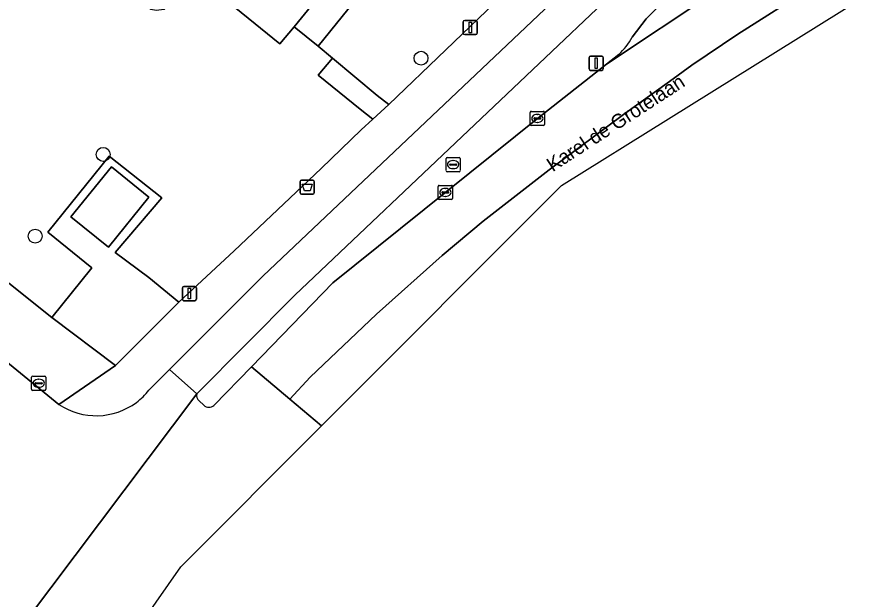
# Model space of a CAD drawing. Extents: x 159674 to 160531, y 382172 to 382904.
# Drawn here: x 160403.6 to 160463.2, y 382615.6 to 382656.6 of the extents above; entities that cross this region are included whole.
import ezdxf

# ---------------------------------------------------------------- set-up
doc = ezdxf.new("R2010")
doc.units = 0
for name, color, linetype in [('IMGEO_Afvalbak', 7, 'Continuous'), ('IMGEO_Boom', 7, 'Continuous'), ('IMGEO_Fietspad_gesloten', 7, 'Continuous'), ('IMGEO_Groenvoorziening', 7, 'Continuous'), ('IMGEO_Kolk', 7, 'Continuous'), ('IMGEO_Lichtmast', 7, 'Continuous'), ('IMGEO_Openbare_ruimte_label', 7, 'Continuous'), ('IMGEO_Pand', 7, 'Continuous'), ('IMGEO_Rijbaan_lokaal_gesloten', 7, 'Continuous'), ('IMGEO_Rijbaan_lokaal_open', 7, 'Continuous'), ('IMGEO_Rioolput', 7, 'Continuous'), ('IMGEO_Voetpad_open', 7, 'Continuous')]:
    doc.layers.add(name, color=color, linetype=linetype)

msp = doc.modelspace()

# ---------------------------------------------------------------- linework, layer by layer
at = {"layer": 'IMGEO_Afvalbak'}
for p, q in [((160423.555, 382644.212), (160423.555, 382645.012)), ((160423.555, 382645.012), (160423.555, 382644.212)), ((160423.655, 382645.112), (160424.445, 382645.112)), ((160424.445, 382645.112), (160423.655, 382645.112)), ((160424.545, 382645.012), (160424.545, 382644.212)), ((160424.545, 382644.212), (160424.545, 382645.012)), ((160424.445, 382644.112), (160423.655, 382644.112)), ((160423.655, 382644.112), (160424.445, 382644.112))]:
    msp.add_line(p, q, dxfattribs=at)
msp.add_lwpolyline([(160423.698, 382644.826), (160424.402, 382644.826), (160424.253, 382644.356), (160423.847, 382644.356), (160423.698, 382644.826)], dxfattribs=at)
for centre, start, end in [((160423.655, 382645.012), 90, 180), ((160423.655, 382645.012), 90, 180), ((160424.445, 382645.012), 0, 90), ((160424.445, 382645.012), 360, 90), ((160423.655, 382644.212), 180, 270), ((160423.655, 382644.212), 180, 270), ((160424.445, 382644.212), 270, 0), ((160424.445, 382644.212), 270, 0)]:
    msp.add_arc(centre, 0.1, start, end, dxfattribs=at)
at = {"layer": 'IMGEO_Boom'}
for centre in [(160432.057, 382653.687), (160409.684, 382646.916), (160404.9, 382641.156)]:
    msp.add_circle(centre, 0.489, dxfattribs=at)
at = {"layer": 'IMGEO_Fietspad_gesloten'}
msp.add_lwpolyline([(160481.633, 382696.489), (160468.127, 382683.364), (160447.776, 382663.816), (160420.944, 382638.37), (160414.361, 382631.767), (160416.285, 382630.052), (160423.176, 382637.014), (160449.405, 382661.919)], dxfattribs=at)
at = {"layer": 'IMGEO_Groenvoorziening'}
for points in [[(160458.672, 382690.773), (160458.911, 382690.581), (160460.799, 382692.927), (160459.501, 382693.982), (160460.055, 382694.663), (160458.322, 382696.07), (160458.645, 382696.467), (160455.839, 382698.746), (160454.066, 382700.186), (160451.285, 382696.761), (160455.9, 382693.013), (160456.251, 382693.445), (160457.39, 382692.52), (160454.167, 382688.552), (160441.841, 382673.375), (160439.126, 382675.58), (160433.895, 382669.14), (160423.117, 382655.907), (160424.815, 382654.532), (160438.917, 382671.995), (160441.694, 382669.745)], [(160465.663, 382685.146), (160458.911, 382690.581), (160458.672, 382690.773), (160441.694, 382669.745), (160438.917, 382671.995), (160424.815, 382654.532), (160425.817, 382653.69), (160428.959, 382651.052), (160429.794, 382650.429), (160445.842, 382665.847)]]:
    msp.add_lwpolyline(points, close=True, dxfattribs=at)
msp.add_lwpolyline([(160378.286, 382657.664), (160406.072, 382635.422), (160408.896, 382638.927), (160405.782, 382641.438), (160410.1, 382646.796), (160413.826, 382643.859), (160410.536, 382640.006), (160412.902, 382638.241), (160415.013, 382636.511), (160418.91, 382640.121), (160425.018, 382645.922), (160427.834, 382648.645), (160428.66, 382649.405), (160427.78, 382650.092), (160424.82, 382652.503), (160425.817, 382653.69), (160424.815, 382654.532), (160423.117, 382655.907), (160422.13, 382654.694), (160416.298, 382659.444)], dxfattribs=at)
at = {"layer": 'IMGEO_Kolk'}
for p, q in [((160439.742, 382649.022), (160439.742, 382649.874)), ((160439.817, 382649.948), (160440.669, 382649.948)), ((160440.23, 382649.728), (160440.255, 382649.728)), ((160440.743, 382649.874), (160440.743, 382649.022)), ((160440.001, 382649.442), (160440.001, 382649.454)), ((160440.439, 382649.405), (160440.041, 382649.405)), ((160440.044, 382649.491), (160440.442, 382649.491)), ((160440.253, 382649.168), (160440.228, 382649.168)), ((160440.485, 382649.454), (160440.485, 382649.442)), ((160440.669, 382648.948), (160439.817, 382648.948)), ((160433.269, 382643.81), (160433.269, 382644.662)), ((160433.344, 382644.736), (160434.196, 382644.736)), ((160433.528, 382644.23), (160433.528, 382644.242)), ((160433.966, 382644.193), (160433.568, 382644.193)), ((160433.571, 382644.279), (160433.969, 382644.279)), ((160433.757, 382644.516), (160433.782, 382644.516)), ((160434.012, 382644.242), (160434.012, 382644.23)), ((160434.27, 382644.662), (160434.27, 382643.81)), ((160434.196, 382643.736), (160433.344, 382643.736)), ((160433.78, 382643.956), (160433.755, 382643.956)), ((160404.652, 382630.371), (160404.652, 382631.223)), ((160404.727, 382631.297), (160405.579, 382631.297)), ((160405.653, 382631.223), (160405.653, 382630.371)), ((160404.911, 382630.791), (160404.911, 382630.803)), ((160405.349, 382630.754), (160404.951, 382630.754)), ((160404.954, 382630.84), (160405.352, 382630.84)), ((160405.163, 382630.517), (160405.138, 382630.517)), ((160405.14, 382631.077), (160405.165, 382631.077)), ((160405.395, 382630.803), (160405.395, 382630.791)), ((160405.579, 382630.297), (160404.727, 382630.297))]:
    msp.add_line(p, q, dxfattribs=at)
for points in [[(160439.742, 382649.022), (160439.742, 382649.874)], [(160439.817, 382649.948), (160440.669, 382649.948)], [(160440.743, 382649.874), (160440.743, 382649.022)], [(160440.669, 382648.948), (160439.817, 382648.948)], [(160433.269, 382643.81), (160433.269, 382644.662)], [(160433.344, 382644.736), (160434.196, 382644.736)], [(160434.27, 382644.662), (160434.27, 382643.81)], [(160434.196, 382643.736), (160433.344, 382643.736)], [(160404.652, 382630.371), (160404.652, 382631.223)], [(160404.727, 382631.297), (160405.579, 382631.297)], [(160405.653, 382631.223), (160405.653, 382630.371)], [(160405.579, 382630.297), (160404.727, 382630.297)]]:
    msp.add_lwpolyline(points, dxfattribs=at)
for centre, radius, start, end in [((160439.819, 382649.872), 0.0765, 91.55205, 178.44795), ((160439.819, 382649.872), 0.0765, 91.55205, 178.44795), ((160440.667, 382649.872), 0.0765, 1.55205, 88.44795), ((160440.667, 382649.872), 0.0765, 1.55205, 88.44795), ((160439.819, 382649.024), 0.0765, 181.55205, 268.44795), ((160439.819, 382649.024), 0.0765, 181.55205, 268.44795), ((160440.041, 382649.451), 0.0403, 85.87752, 175.75265), ((160440.038, 382649.441), 0.0366, 178.93798, 274.71019), ((160440.442, 382649.448), 0.043, 264.86636, 352.45326), ((160440.446, 382649.453), 0.0386, 1.73085, 96.63898), ((160440.667, 382649.024), 0.0765, 271.55205, 358.44795), ((160440.667, 382649.024), 0.0765, 271.55205, 358.44795), ((160433.346, 382644.66), 0.0765, 91.55205, 178.44795), ((160433.346, 382644.66), 0.0765, 91.55205, 178.44795), ((160433.568, 382644.239), 0.0403, 85.87752, 175.75265), ((160433.565, 382644.229), 0.0366, 178.93798, 274.71019), ((160433.969, 382644.236), 0.043, 264.86636, 352.45326), ((160433.973, 382644.241), 0.0386, 1.73085, 96.63898), ((160434.194, 382644.66), 0.0765, 1.55205, 88.44795), ((160434.194, 382644.66), 0.0765, 1.55205, 88.44795), ((160433.346, 382643.812), 0.0765, 181.55205, 268.44795), ((160433.346, 382643.812), 0.0765, 181.55205, 268.44795), ((160434.194, 382643.812), 0.0765, 271.55205, 358.44795), ((160434.194, 382643.812), 0.0765, 271.55205, 358.44795), ((160404.729, 382631.221), 0.0765, 91.55205, 178.44795), ((160404.729, 382631.221), 0.0765, 91.55205, 178.44795), ((160405.577, 382631.221), 0.0765, 1.55205, 88.44795), ((160405.577, 382631.221), 0.0765, 1.55205, 88.44795), ((160404.951, 382630.8), 0.0403, 85.87752, 175.75265), ((160404.948, 382630.79), 0.0366, 178.93798, 274.71019), ((160405.352, 382630.797), 0.043, 264.86636, 352.45326), ((160405.356, 382630.802), 0.0386, 1.73085, 96.63898), ((160404.729, 382630.373), 0.0765, 181.55205, 268.44795), ((160404.729, 382630.373), 0.0765, 181.55205, 268.44795), ((160405.577, 382630.373), 0.0765, 271.55205, 358.44795), ((160405.577, 382630.373), 0.0765, 271.55205, 358.44795)]:
    msp.add_arc(centre, radius, start, end, dxfattribs=at)
for centre, major_axis, ratio, start_param, end_param in [((160440.229, 382649.448), (-0.387, 0.002), 0.722429, 4.712389, 7.853982), ((160440.254, 382649.448), (-0.39, 0.002), 0.717154, 1.570796, 4.712389), ((160433.756, 382644.236), (-0.387, 0.002), 0.722429, 4.712389, 7.853982), ((160433.781, 382644.236), (-0.39, 0.002), 0.717154, 1.570796, 4.712389), ((160405.139, 382630.797), (-0.387, 0.002), 0.722429, 4.712389, 7.853982), ((160405.164, 382630.797), (-0.39, 0.002), 0.717154, 1.570796, 4.712389)]:
    msp.add_ellipse(centre, major_axis=major_axis, ratio=ratio, start_param=start_param, end_param=end_param, dxfattribs=at)
at = {"layer": 'IMGEO_Lichtmast'}
for p, q in [((160435.027, 382655.45), (160435.027, 382656.25)), ((160435.027, 382656.25), (160435.027, 382655.45)), ((160435.127, 382656.35), (160435.917, 382656.35)), ((160435.917, 382656.35), (160435.127, 382656.35)), ((160436.017, 382656.25), (160436.017, 382655.45)), ((160436.017, 382655.45), (160436.017, 382656.25)), ((160435.917, 382655.35), (160435.127, 382655.35)), ((160435.127, 382655.35), (160435.917, 382655.35)), ((160443.891, 382652.93), (160443.891, 382653.73)), ((160443.891, 382653.73), (160443.891, 382652.93)), ((160443.991, 382653.83), (160444.781, 382653.83)), ((160444.781, 382653.83), (160443.991, 382653.83)), ((160444.881, 382653.73), (160444.881, 382652.93)), ((160444.881, 382652.93), (160444.881, 382653.73)), ((160444.781, 382652.83), (160443.991, 382652.83)), ((160443.991, 382652.83), (160444.781, 382652.83)), ((160415.259, 382636.714), (160415.259, 382637.514)), ((160415.259, 382637.514), (160415.259, 382636.714)), ((160415.359, 382637.614), (160416.149, 382637.614)), ((160416.149, 382637.614), (160415.359, 382637.614)), ((160416.249, 382637.514), (160416.249, 382636.714)), ((160416.249, 382636.714), (160416.249, 382637.514)), ((160416.149, 382636.614), (160415.359, 382636.614)), ((160415.359, 382636.614), (160416.149, 382636.614))]:
    msp.add_line(p, q, dxfattribs=at)
for points in [[(160435.447, 382656.225), (160435.597, 382656.225), (160435.597, 382655.475), (160435.447, 382655.475), (160435.447, 382656.225)], [(160444.311, 382653.705), (160444.461, 382653.705), (160444.461, 382652.955), (160444.311, 382652.955), (160444.311, 382653.705)], [(160415.679, 382637.489), (160415.829, 382637.489), (160415.829, 382636.739), (160415.679, 382636.739), (160415.679, 382637.489)]]:
    msp.add_lwpolyline(points, dxfattribs=at)
for centre, start, end in [((160435.127, 382656.25), 90, 180), ((160435.127, 382656.25), 90, 180), ((160435.917, 382656.25), 0, 90), ((160435.917, 382656.25), 360, 90), ((160435.127, 382655.45), 180, 270), ((160435.127, 382655.45), 180, 270), ((160435.917, 382655.45), 270, 0), ((160435.917, 382655.45), 270, 0), ((160443.991, 382653.73), 90, 180), ((160443.991, 382653.73), 90, 180), ((160444.781, 382653.73), 0, 90), ((160444.781, 382653.73), 360, 90), ((160443.991, 382652.93), 180, 270), ((160443.991, 382652.93), 180, 270), ((160444.781, 382652.93), 270, 0), ((160444.781, 382652.93), 270, 0), ((160415.359, 382637.514), 90, 180), ((160415.359, 382637.514), 90, 180), ((160416.149, 382637.514), 0, 90), ((160416.149, 382637.514), 360, 90), ((160415.359, 382636.714), 180, 270), ((160415.359, 382636.714), 180, 270), ((160416.149, 382636.714), 270, 0), ((160416.149, 382636.714), 270, 0)]:
    msp.add_arc(centre, 0.1, start, end, dxfattribs=at)
at = {"layer": 'IMGEO_Pand'}
msp.add_lwpolyline([(160410.069, 382640.383), (160412.912, 382643.91), (160410.265, 382646.044), (160407.422, 382642.517)], close=True, dxfattribs=at)
at = {"layer": 'IMGEO_Rijbaan_lokaal_gesloten'}
for points in [[(160425.058, 382627.793), (160441.937, 382644.719), (160449.46, 382649.412), (160520.291, 382693.593), (160520.082, 382694.258), (160514.905, 382691.206), (160507.904, 382687.094), (160484.466, 382673.393), (160473.282, 382666.869), (160464.534, 382661.746), (160459.546, 382658.695), (160454.36, 382655.379), (160451.123, 382653.197), (160449.54, 382652.06), (160446.294, 382649.734), (160441.082, 382645.84), (160436.434, 382642.22), (160433.555, 382639.797), (160428.922, 382635.656), (160424.246, 382631.216), (160422.817, 382629.684), (160425.058, 382627.793)], [(160473.663, 382671.145), (160462.423, 382664.487), (160452.724, 382658.364), (160445.113, 382653.274), (160440.243, 382649.448), (160425.843, 382637.873), (160420.117, 382631.963), (160422.817, 382629.684), (160424.246, 382631.216), (160428.922, 382635.656), (160433.555, 382639.797), (160436.434, 382642.22), (160441.082, 382645.84), (160446.294, 382649.734), (160449.54, 382652.06), (160451.123, 382653.197), (160454.36, 382655.379), (160459.546, 382658.695), (160464.534, 382661.746)], [(160406.571, 382629.307), (160384.589, 382647.265)], [(160401.904, 382615.599), (160404.299, 382614.103), (160416.285, 382630.052), (160414.361, 382631.767), (160412.906, 382630.307)], [(160406.309, 382605.199), (160415.161, 382617.869), (160425.058, 382627.793), (160422.817, 382629.684), (160420.117, 382631.963), (160417.475, 382629.237)], [(160416.285, 382630.052), (160404.299, 382614.103)], [(160416.763, 382629.246), (160416.439, 382629.571)]]:
    msp.add_lwpolyline(points, dxfattribs=at)
for centre, radius, start, end in [((160409.238, 382633.2), 4.672, 306.67419, 321.73803), ((160416.659, 382629.907), 0.402, 158.78821, 236.71842), ((160409.196, 382633.245), 4.733, 236.31434, 306.75079), ((160417.124, 382629.637), 0.533, 227.31846, 311.23313)]:
    msp.add_arc(centre, radius, start, end, dxfattribs=at)
at = {"layer": 'IMGEO_Rijbaan_lokaal_open'}
for points in [[(160468.98, 382678.92), (160469.594, 382677.622), (160457.254, 382665.708), (160447.892, 382656.462), (160446.923, 382655.165)], [(160445.973, 382653.947), (160445.113, 382653.274), (160452.724, 382658.364), (160462.423, 382664.487), (160473.663, 382671.145)]]:
    msp.add_lwpolyline(points, dxfattribs=at)
msp.add_arc((160442.179, 382657.885), 5.468, 313.92742, 330.16646, dxfattribs=at)
at = {"layer": 'IMGEO_Rioolput'}
for p, q in [((160433.816, 382645.77), (160433.816, 382646.622)), ((160433.891, 382646.696), (160434.743, 382646.696)), ((160434.817, 382646.622), (160434.817, 382645.77)), ((160434.075, 382646.19), (160434.075, 382646.202)), ((160434.513, 382646.153), (160434.115, 382646.153)), ((160434.118, 382646.239), (160434.516, 382646.239)), ((160434.304, 382646.476), (160434.329, 382646.476)), ((160434.559, 382646.202), (160434.559, 382646.19)), ((160434.743, 382645.696), (160433.891, 382645.696)), ((160434.327, 382645.916), (160434.302, 382645.916))]:
    msp.add_line(p, q, dxfattribs=at)
for points in [[(160433.816, 382645.77), (160433.816, 382646.622)], [(160433.891, 382646.696), (160434.743, 382646.696)], [(160434.817, 382646.622), (160434.817, 382645.77)], [(160434.743, 382645.696), (160433.891, 382645.696)]]:
    msp.add_lwpolyline(points, dxfattribs=at)
for centre, radius, start, end in [((160433.893, 382646.62), 0.0765, 91.55205, 178.44795), ((160433.893, 382646.62), 0.0765, 91.55205, 178.44795), ((160434.741, 382646.62), 0.0765, 1.55205, 88.44795), ((160434.741, 382646.62), 0.0765, 1.55205, 88.44795), ((160434.115, 382646.199), 0.0403, 85.87752, 175.75265), ((160434.112, 382646.189), 0.0366, 178.93798, 274.71019), ((160434.516, 382646.196), 0.043, 264.86636, 352.45326), ((160434.52, 382646.201), 0.0386, 1.73085, 96.63898), ((160433.893, 382645.772), 0.0765, 181.55205, 268.44795), ((160433.893, 382645.772), 0.0765, 181.55205, 268.44795), ((160434.741, 382645.772), 0.0765, 271.55205, 358.44795), ((160434.741, 382645.772), 0.0765, 271.55205, 358.44795)]:
    msp.add_arc(centre, radius, start, end, dxfattribs=at)
for centre, major_axis, ratio, start_param, end_param in [((160434.303, 382646.196), (-0.387, 0.002), 0.722429, 4.712389, 7.853982), ((160434.328, 382646.196), (-0.39, 0.002), 0.717154, 1.570796, 4.712389)]:
    msp.add_ellipse(centre, major_axis=major_axis, ratio=ratio, start_param=start_param, end_param=end_param, dxfattribs=at)
at = {"layer": 'IMGEO_Voetpad_open'}
for points in [[(160412.672, 382657.428), (160413.038, 382657.145), (160413.412, 382657.081), (160413.989, 382657.135), (160414.15, 382657.284), (160416.075, 382659.625), (160416.298, 382659.444), (160422.13, 382654.694), (160423.117, 382655.907), (160433.895, 382669.14), (160439.126, 382675.58), (160441.841, 382673.375), (160454.167, 382688.552), (160457.39, 382692.52), (160456.251, 382693.445), (160455.9, 382693.013)], [(160420.944, 382638.37), (160447.776, 382663.816), (160468.127, 382683.364), (160465.853, 382685.33), (160465.663, 382685.146), (160445.842, 382665.847), (160429.794, 382650.429), (160428.66, 382649.405), (160427.834, 382648.645), (160425.018, 382645.922), (160418.91, 382640.121), (160415.013, 382636.511), (160410.553, 382632.042), (160406.571, 382629.307)], [(160470.59, 382682.442), (160468.048, 382679.851), (160449.405, 382661.919), (160423.176, 382637.014), (160416.285, 382630.052)], [(160447.892, 382656.462), (160457.254, 382665.708), (160469.594, 382677.622), (160468.98, 382678.92)], [(160446.923, 382655.165), (160447.892, 382656.462)], [(160417.475, 382629.237), (160420.117, 382631.963), (160425.843, 382637.873), (160440.243, 382649.448), (160445.113, 382653.274), (160445.973, 382653.947)], [(160412.906, 382630.307), (160414.361, 382631.767), (160420.944, 382638.37)], [(160416.439, 382629.571), (160416.763, 382629.246)]]:
    msp.add_lwpolyline(points, dxfattribs=at)
for points in [[(160378.286, 382657.664), (160376.754, 382655.854), (160377.969, 382654.877), (160376.836, 382653.466), (160382.462, 382648.966), (160384.589, 382647.265), (160406.571, 382629.307), (160410.553, 382632.042), (160406.072, 382635.422)], [(160425.817, 382653.69), (160424.82, 382652.503), (160427.78, 382650.092), (160428.66, 382649.405), (160429.794, 382650.429), (160428.959, 382651.052)], [(160410.536, 382640.006), (160413.826, 382643.859), (160410.1, 382646.796), (160405.782, 382641.438), (160408.896, 382638.927), (160406.072, 382635.422), (160410.553, 382632.042), (160415.013, 382636.511), (160412.902, 382638.241)], [(160410.069, 382640.383), (160407.422, 382642.517), (160410.265, 382646.044), (160412.912, 382643.91)]]:
    msp.add_lwpolyline(points, close=True, dxfattribs=at)
for centre, radius, start, end in [((160442.179, 382657.885), 5.468, 313.92742, 330.16646), ((160409.238, 382633.2), 4.672, 306.67419, 321.73803), ((160416.659, 382629.907), 0.402, 158.78821, 236.71842), ((160409.196, 382633.245), 4.733, 236.31434, 306.75079), ((160417.124, 382629.637), 0.533, 227.31846, 311.23313)]:
    msp.add_arc(centre, radius, start, end, dxfattribs=at)

# ---------------------------------------------------------------- texts
at = {"layer": 'IMGEO_Openbare_ruimte_label'}
msp.add_text('Karel de Grotelaan', height=1, rotation=33.03828, dxfattribs=at).set_placement((160441.316, 382645.656))

doc.saveas('drawing.dxf')
